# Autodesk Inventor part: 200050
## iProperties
Created: 2007-10
Part Number: 200050
Document SubType Name: Modeling
Designer: TH
Density: 7.85 g/cm^3
Mass: 510.334 g
Surface Area: 671.811 cm^2
Volume: 65.0106 cm^3
Material: Steel
Description: RAIL SIDE - LEFT INNER
Component Category: Lower Component
Author: TH
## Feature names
1. Extrusion1
2. Fillet1
3. Extrusion2
4. Extrusion3
5. Fillet2
6. Fillet3
7. Extrusion4
8. Fillet4
9. Fillet5
10. Hole1
11. Hole2
